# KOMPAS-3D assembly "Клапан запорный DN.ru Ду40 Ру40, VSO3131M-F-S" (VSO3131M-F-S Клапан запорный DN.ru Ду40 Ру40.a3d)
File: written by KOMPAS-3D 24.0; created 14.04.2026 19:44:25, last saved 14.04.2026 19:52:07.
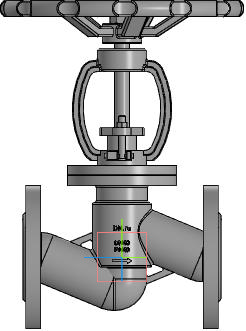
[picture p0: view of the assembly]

Document properties: Автор: R2D2; Полное имя файла: E:\Работа\Зайцев\VSO3131M-F-S Клапан запорный DN.ru Ду15-100 Ру40\DN40\исходные материалы\VSO3131M-F-S Клапан запорный DN.ru Ду40 Ру40.a3d

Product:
- Component [detail]: Корпус  | qty 1  | Масса: 6.9; Автор: R2D2; source file: Корпус.m3d
- Component [detail]: Клапан запорный DN.ru Ду40 Ру16  | designation VSO1121M-F-S  | qty 1  | Масса: 9.32; Раздел спецификации: Прочие изделия; Примечание: D090-01946; Автор: R2D2; source file: 2.m3d
- Part/product: Клапан запорный DN.ru Ду40 Ру40  | designation VSO3131M-F-S
    Масса: 9.54
    Раздел спецификации: Прочие изделия
    Примечание: D090-02141

Referenced files in E:\Работа\Зайцев\VSO3131M-F-S Клапан запорный DN.ru Ду15-100 Ру40\DN40\исходные материалы\: Корпус.m3d, 2.m3d
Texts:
  VSO3131M-F-S
  VSO1121M-F-S Клапан запорный DN.ru Ду40 Ру16
  Ось Y.Начало координат
  Плоскость XY.Начало координат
